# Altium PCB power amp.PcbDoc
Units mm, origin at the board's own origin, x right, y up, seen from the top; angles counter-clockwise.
Board outline 166.75 x 72.39 mm, 2 copper layers (Top Layer, Bottom Layer); 34 components, 39 nets, 126 pads, 16 vias.
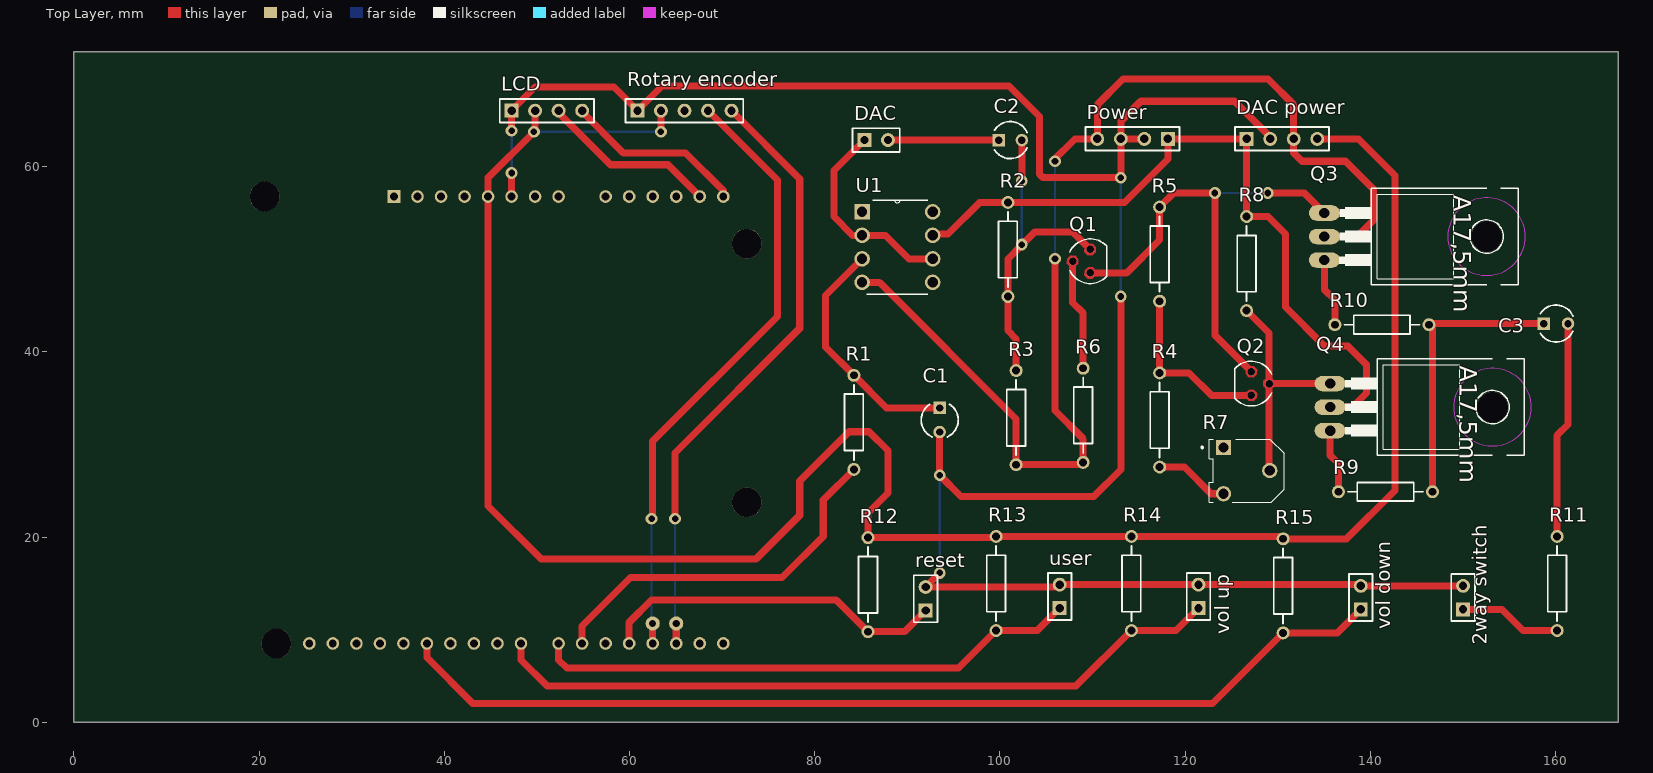
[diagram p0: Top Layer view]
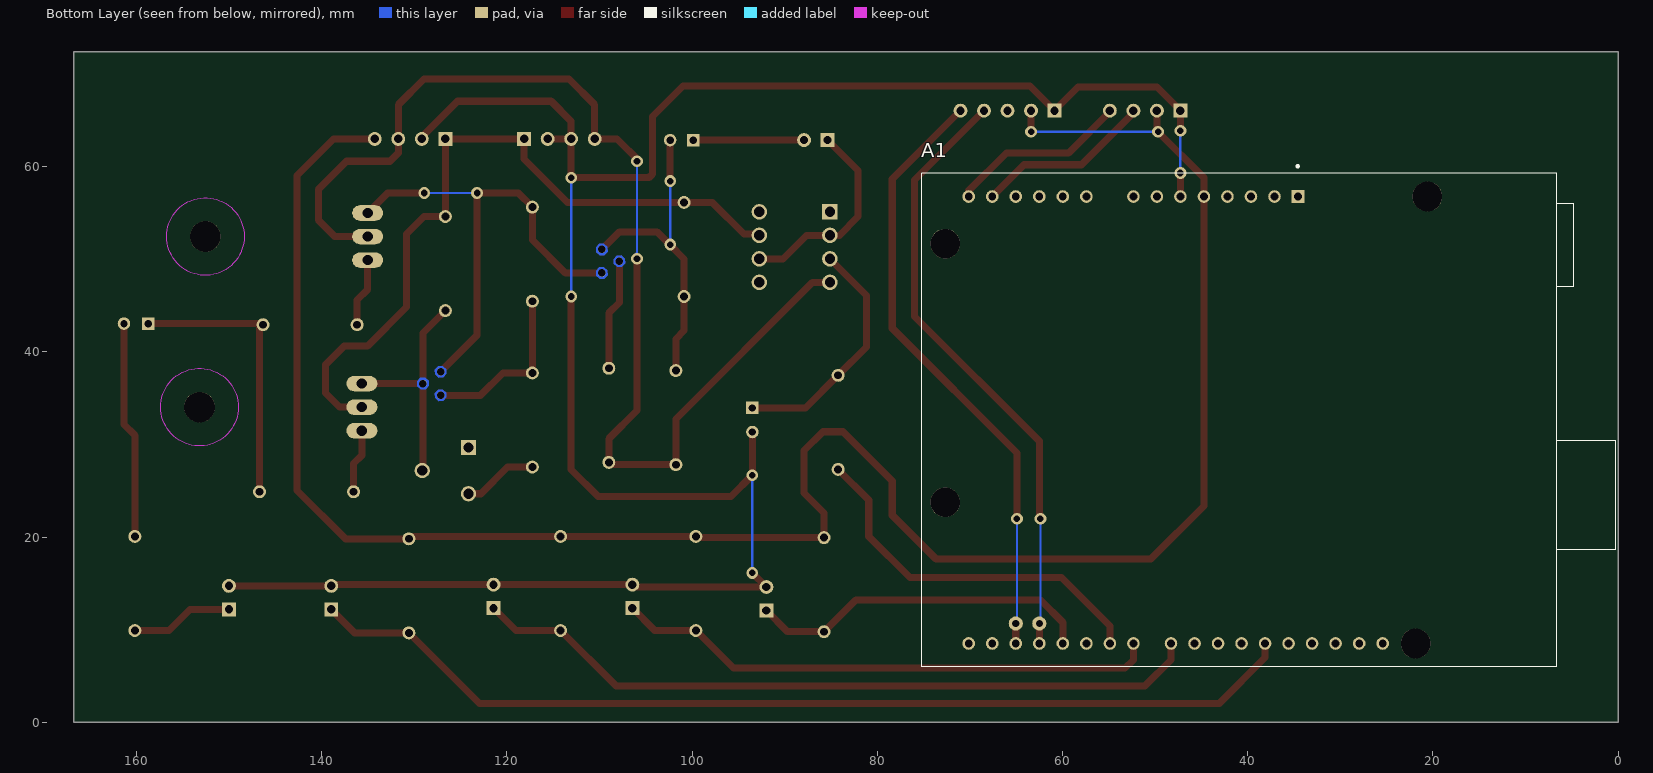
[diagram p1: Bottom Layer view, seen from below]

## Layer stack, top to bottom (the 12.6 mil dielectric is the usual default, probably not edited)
Top Solder: solder mask 0.0102, Solder Resist, Dk 3.5
Top Layer: signal copper 0.0356
Dielectric 1: dielectric 0.32, FR-4, Dk 4.8
Bottom Layer: signal copper 0.0356
Bottom Solder: solder mask 0.0102, Solder Resist, Dk 3.5

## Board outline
0,0 166.751,0 166.751,72.39 0,72.39

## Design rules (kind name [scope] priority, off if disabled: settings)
Clearance [All] p1: gap=0.254 ignorepadtopadclearanceinfootprint=FALSE except(0: Arc-Hole Track-Hole SMDPad-Hole THPad-Hole Via-Hole Fill-Hole Poly-Hole Region-Hole Text-Hole; 0.508: Arc-Arc Arc-Track Arc-THPad Track-Track Track-THPad)
PolygonConnect [All] p1: connectstyle=Relief reliefconductorwidth=0.254 reliefentries=4 polygonreliefangle="90 Angle" airgapwidth=0.254
RoutingVias [All] p1: holewidth=0.711 width=1.27 viastyle="Through Hole" minholewidth=0.711 minwidth=1.27 maxholewidth=0.711 maxwidth=1.27
SolderMaskExpansion [All] p1: expansion=0.102
Width [All] p1: maxlimit=0.813 minlimit=0.254 preferedwidth=0.762 toplayer_minwidth=0.711 bottomlayer_maxwidth=0.254 bottomlayer_prefwidth=0.254 minimp=50.000000 maximp=50.000000 favimp=50.000000
30 further rules are at their usual default settings.

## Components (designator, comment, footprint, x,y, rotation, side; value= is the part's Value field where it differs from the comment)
"2way switch" "Header 2" HDR1X2 150.008,12.192 r90 top
A1 "ARDUINO_UNO_REV3_DEVELOPMENT_BOARD" *ARDUINO_UNO_REV3_DEVELOPMENT_BOARD 40.915,32.639 r270 bottom
C1 "Cap2" CAPR5-4X5#1 93.493,32.639 r270 top value=0.01uF
C2 "Cap2" CAPR5-4X5#2 101.113,62.865 r0 top value=47uF
C3 "Cap2" CAPR5-4X5#1 160.041,43.053 r0 top value=33uF
DAC "Header 2" HDR1X2 85.365,62.865 r0 top
"DAC power" "Header 4" HDR1X4 126.64,62.992 r0 top
LCD "Header 4" HDR1X4 47.265,66.04 r0 top
Power "Header 4" HDR1X4 118.131,62.992 r180 top
Q1 "BC640" *SOT54D_BC640(Primary) 109.749,49.784 r90 top
Q2 "BC639" *SOT54D_BC639(Primary) 127.148,36.576 r270 top
Q3 "TIP125" *TO220 141.372,52.451 r270 top
Q4 "TIP120" *TO220AH_TIP120(Primary) 142.007,34.036 r270 top
R1 "Res2" AXIAL-0.4 84.222,32.385 r90 top value=12K
R2 "Res2" AXIAL-0.4 100.859,51.054 r90 top value=22K
R3 "Res2" AXIAL-0.4 101.748,32.893 r90 top value=15K
R4 "Res2" AXIAL-0.4 117.242,32.639 r270 top value=2.2K
R5 "Res2" AXIAL-0.4 117.242,50.546 r270 top value=4.7K
R6 "Res2" AXIAL-0.4 108.987,33.147 r90 top value=4.7K
R7 "3306F-1-104" *TRIM_3306F-1-104 126.64,27.178 r180 top
R8 "Res2" AXIAL-0.4 126.64,49.53 r90 top value=10K
R9 "Res2" AXIAL-0.4 141.626,24.892 r180 top value=1
R10 "Res2" AXIAL-0.4 141.245,42.926 r0 top value=1
R11 "Res2" AXIAL-0.4 160.168,14.986 r90 top value=1K
R12 "Res2" AXIAL-0.4 85.746,14.859 r270 top value=12K
R13 "Res2" AXIAL-0.4 99.589,14.986 r270 top value=12K
R14 "Res2" AXIAL-0.4 114.194,14.986 r270 top value=12K
R15 "Res2" AXIAL-0.4 130.577,14.732 r270 top value=12K
reset "Header 2" HDR1X2 91.969,12.065 r90 top
"Rotary encoder" "Header 5" HDR1X5 60.854,66.04 r0 top
U1 "TL071CP" *DIP254P762X508-8 92.731,47.498 r0 top
user "Header 2" HDR1X2 106.447,12.319 r90 top
"vol down" "Header 2" HDR1X2 138.959,12.192 r90 top
"vol up" "Header 2" HDR1X2 121.433,12.319 r90 top

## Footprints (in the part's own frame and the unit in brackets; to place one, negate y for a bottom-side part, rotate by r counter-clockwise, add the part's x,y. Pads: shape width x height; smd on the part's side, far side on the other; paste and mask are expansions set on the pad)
*ARDUINO_UNO_REV3_DEVELOPMENT_BOARD [mm]
  rect 1.358x1.358 hole 0.85: 1(-24.13,6.35)
  round 1.358 hole 0.85: 2(-24.13,3.81) 3(-24.13,1.27) 4(-24.13,-1.27) 5(-24.13,-3.81) 6(-24.13,-6.35) 7(-24.13,-8.89) 8(-24.13,-11.43) 9(-24.13,-16.51) 10(-24.13,-19.05) 11(-24.13,-21.59) 12(-24.13,-24.13) 13(-24.13,-26.67) 14(-24.13,-29.21) 15(24.13,-29.21) 16(24.13,-26.67) 17(24.13,-24.13) 18(24.13,-21.59) 19(24.13,-19.05) 20(24.13,-16.51) 21(24.13,-13.97) 22(24.13,-11.43) 23(24.13,-7.366) 24(24.13,-4.826) 25(24.13,-2.286) 26(24.13,0.254) 27(24.13,2.794) 28(24.13,5.334) 29(24.13,7.874) 30(24.13,10.414) 31(24.13,12.954) 32(24.13,15.494)
  round 3.2 hole 3.2 unplated: None(-24.13,20.32) None(-19.05,-31.75) None(8.89,-31.75) None(24.13,19.05)
  silkscreen extent -27.52,-34.29 26.67,40.64
*DIP254P762X508-8 [mil]
  rect 66x66 hole 44: 1(-300,300)
  round 66 hole 44: 2(-300,200) 3(-300,100) 4(-300,0) 5(0,0) 6(0,100) 7(0,200) 8(0,300)
  silkscreen extent -280,-50 -20,350
*SOT54D_BC639(Primary) [mil]
  round 32 hole 32: B(50,0) C(0,75) E(-50,0)
  Top Layer region: -25.57,8.89 -39.01,23.56 -58.89,24.43 -73.56,10.99 -74.43,-8.89 -60.99,-23.56 -41.11,-24.43 -26.44,-10.99
  Top Layer region: 24.43,83.89 10.99,98.56 -8.89,99.43 -23.56,85.99 -24.43,66.11 -10.99,51.44 8.89,50.57 23.56,64.01
  Top Layer region: 74.43,8.89 60.99,23.56 41.11,24.43 26.44,10.99 25.57,-8.89 39.01,-23.56 58.89,-24.43 73.56,-10.99
  Bottom Layer region: -25.57,8.89 -39.01,23.56 -58.89,24.43 -73.56,10.99 -74.43,-8.89 -60.99,-23.56 -41.11,-24.43 -26.44,-10.99
  Bottom Layer region: 24.43,83.89 10.99,98.56 -8.89,99.43 -23.56,85.99 -24.43,66.11 -10.99,51.44 8.89,50.57 23.56,64.01
  Bottom Layer region: 74.43,8.89 60.99,23.56 41.11,24.43 26.44,10.99 25.57,-8.89 39.01,-23.56 58.89,-24.43 73.56,-10.99
  Multi-Layer region: -25.57,8.89 -39.01,23.56 -58.89,24.43 -73.56,10.99 -74.43,-8.89 -60.99,-23.56 -41.11,-24.43 -26.44,-10.99
  Multi-Layer region: 24.43,83.89 10.99,98.56 -8.89,99.43 -23.56,85.99 -24.43,66.11 -10.99,51.44 8.89,50.57 23.56,64.01
  Multi-Layer region: 74.43,8.89 60.99,23.56 41.11,24.43 26.44,10.99 25.57,-8.89 39.01,-23.56 58.89,-24.43 73.56,-10.99
  silkscreen extent -95,-70 95,87
*SOT54D_BC640(Primary) [mil]
  round 32 hole 32: B(50,0) C(0,75) E(-50,0)
  Top Layer region: -25.57,8.89 -39.01,23.56 -58.89,24.43 -73.56,10.99 -74.43,-8.89 -60.99,-23.56 -41.11,-24.43 -26.44,-10.99
  Top Layer region: 24.43,83.89 10.99,98.56 -8.89,99.43 -23.56,85.99 -24.43,66.11 -10.99,51.44 8.89,50.57 23.56,64.01
  Top Layer region: 74.43,8.89 60.99,23.56 41.11,24.43 26.44,10.99 25.57,-8.89 39.01,-23.56 58.89,-24.43 73.56,-10.99
  Bottom Layer region: -25.57,8.89 -39.01,23.56 -58.89,24.43 -73.56,10.99 -74.43,-8.89 -60.99,-23.56 -41.11,-24.43 -26.44,-10.99
  Bottom Layer region: 24.43,83.89 10.99,98.56 -8.89,99.43 -23.56,85.99 -24.43,66.11 -10.99,51.44 8.89,50.57 23.56,64.01
  Bottom Layer region: 74.43,8.89 60.99,23.56 41.11,24.43 26.44,10.99 25.57,-8.89 39.01,-23.56 58.89,-24.43 73.56,-10.99
  Multi-Layer region: -25.57,8.89 -39.01,23.56 -58.89,24.43 -73.56,10.99 -74.43,-8.89 -60.99,-23.56 -41.11,-24.43 -26.44,-10.99
  Multi-Layer region: 24.43,83.89 10.99,98.56 -8.89,99.43 -23.56,85.99 -24.43,66.11 -10.99,51.44 8.89,50.57 23.56,64.01
  Multi-Layer region: 74.43,8.89 60.99,23.56 41.11,24.43 26.44,10.99 25.57,-8.89 39.01,-23.56 58.89,-24.43 73.56,-10.99
  silkscreen extent -95,-70 95,87
*TO220 [mil]
  oval 66x132 hole 44: 1(-100,-250) 2(0,-250) 3(100,-250)
  round 130 hole 130 unplated: None(0,440)
  Keep-Out Layer circle w0: c0,440 r165
  Keep-Out Layer circle w0: c0,440 r165
  Keep-Out Layer circle w0: c0,440 r165
  Keep-Out Layer circle w0: c0,440 r165
  Keep-Out Layer circle w0: c0,440 r165
  Keep-Out Layer circle w0: c0,440 r165
  silkscreen extent -205,-185 205,575
*TO220AH_TIP120(Primary) [mil]
  oval 66x132 hole 44: B(-100,-250) C(0,-250) E(100,-250)
  round 130 hole 130 unplated: None(0,440)
  Keep-Out Layer circle w0: c0,440 r165
  Keep-Out Layer circle w0: c0,440 r165
  Keep-Out Layer circle w0: c0,440 r165
  Keep-Out Layer circle w0: c0,440 r165
  Keep-Out Layer circle w0: c0,440 r165
  Keep-Out Layer circle w0: c0,440 r165
  silkscreen extent -205,-185 205,575
*TRIM_3306F-1-104 [mm]
  rect 1.65x1.65 hole 1.1: 1(2.5,-2.5)
  round 1.65 hole 1.1: 2(-2.5,0) 3(2.5,2.5)
  silkscreen extent -4.05,-3.4 4.9,3.4
AXIAL-0.4 [mm] "Axial Device, Thru-Hole; 2 Leads; 0.4 in Pin Spacing"
  round 1.4 hole 0.85: 1(-5.08,0) 2(5.08,0)
  silkscreen extent -4.06,-1.02 4.06,1.02
CAPR5-4X5#1 [mm] "Capacitor; 2 Leads"
  rect 1.35x1.35 hole 0.8: 1(-1.3,0)
  round 1.35 hole 0.8: 2(1.3,0)
  silkscreen extent -1.69,-2 1.82,2
CAPR5-4X5#2 [mm] "Capacitor; 2 Leads"
  rect 1.35x1.35 hole 0.8: 1(-1.25,0)
  round 1.35 hole 0.8: 2(1.25,0)
  silkscreen extent -1.69,-2 1.82,2
HDR1X2 [mm] "Connector; Header; 2 Position"
  rect 1.5x1.5 hole 0.9: 1(0,0)
  round 1.5 hole 0.9: 2(2.54,0)
  silkscreen extent -1.27,-1.27 3.81,1.27
HDR1X4 [mm] "Connector; Header; 4 Position"
  rect 1.5x1.5 hole 0.9: 1(0,0)
  round 1.5 hole 0.9: 2(2.54,0) 3(5.08,0) 4(7.62,0)
  silkscreen extent -1.27,-1.27 8.89,1.27
HDR1X5 [mm] "Connector; Header; 5 Position"
  rect 1.5x1.5 hole 0.9: 1(0,0)
  round 1.5 hole 0.9: 2(2.54,0) 3(5.08,0) 4(7.62,0) 5(10.16,0)
  silkscreen extent -1.27,-1.27 11.43,1.27

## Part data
"2way switch" DAC reset user "vol down" "vol up": "Header, 2-Pin"
A1: "Plated Through Hole Protoboard Arduino Mega Platform Evaluation Expansion Board", Package=None
C1 C2 C3: "Capacitor"
"DAC power" LCD Power: "Header, 4-Pin"
Q1: "Bipolar _BJT_ Transistor PNP 80V 500mA 150MHz 625mW Through Hole TO-92-3", Package="TO-92 Continental Device"
Q2: "Bipolar _BJT_ Transistor NPN 80V 1A 200MHz 625mW Through Hole TO-92-3", Package="TO-92 Continental Device"
Q3: "Bipolar _BJT_ Transistor PNP - Darlington 60V 5A 2W Through Hole TO-220-3", Package="TO-220 Fairchild Semiconductor"
Q4: "Bipolar _BJT_ Transistor NPN - Darlington 60V 5A 2W Through Hole TO-220-3", Package="TO-220-3 Bourns"
R1 R2 R3 R4 R5 R6 R8 R9 R10 R11 R12 R13 R14 R15: "Resistor"
R7: "100 kOhms 0.2W, 1/5W PC Pins Through Hole Trimmer Potentiometer Cermet 1 Turn Top Adjustment", Package="6432 Bourns"
"Rotary encoder": "Header, 5-Pin"
U1: "J-FET Amplifier 1 Circuit 8-PDIP", Package="DIP-8 Texas Instruments"

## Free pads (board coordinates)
  round 1.524 hole 0.762: 2(62.505,10.668) 3(65.045,10.668)

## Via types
v1: diameter 1.27, hole 0.711, Top Layer to Bottom Layer, 16 vias

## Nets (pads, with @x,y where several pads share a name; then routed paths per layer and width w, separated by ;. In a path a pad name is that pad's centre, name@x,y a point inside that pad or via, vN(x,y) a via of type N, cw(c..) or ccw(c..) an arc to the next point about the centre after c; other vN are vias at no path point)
+5V: "DAC power.4" "Rotary encoder.2" A1.5 LCD.2 R12.1 R13.1 R14.1 R15.1 | length 228.2
  Top Layer w0.762: v1@49.551,63.881 v1(49.678,63.754) ; LCD.2@49.805,65.532 49.805,63.881 v1(49.678,63.754) ; v1(63.394,63.754) 63.394,66.04 ; 134.26,62.992 138.705,62.992 142.642,59.055 142.642,25.019 137.435,19.812 R15.1 130.323,20.066 R14.1 R13.1 99.462,19.939 R12.1 85.746,22.606 87.905,24.765 87.905,29.337 85.873,31.369 83.714,31.369 78.38,26.035 78.38,22.352 73.681,17.653 50.44,17.653 44.725,23.368 A1.5 44.725,58.801 v1(49.678,63.754)
  Bottom Layer w0.254: v1(49.678,63.754) v1(63.394,63.754)
+15V: "DAC power.1" Power.1 Q4.C R2.2 R8.2 U1.7 | length 79.7
  Top Layer w0.762: U1.7 92.858,52.705 94.382,52.705 97.811,56.134 R2.2 113.432,56.134 118.131,60.833 Power.1 126.64,62.992 R8.2 128.926,54.61 130.831,52.705 130.831,44.831 135.022,40.64 137.562,40.64 139.594,38.608 139.594,35.56 138.07,34.036 Q4.C
-15V: "DAC power.3" Power.4 Q3.2 R3.1 R6.1 U1.4 | length 127.2
  Top Layer w0.762: U1.4 87.016,47.498 101.748,32.766 R3.1 108.86,27.813 R6.1@108.987,27.94 ; v1(105.939,50.038) 105.939,33.655 108.987,30.607 R6.1 ; v1(105.939,60.579) 105.685,60.579 108.098,62.992 Power.4 110.511,66.675 113.305,69.469 128.926,69.469 131.72,66.675 131.72,62.992 131.72,61.468 132.609,60.579 137.308,60.579 140.356,57.531 140.356,54.229 138.578,52.451 Q3.2
  Bottom Layer w0.254: v1(105.939,50.038) 106.256,50.355 105.939,50.673 v1(105.939,60.579)
A0: A1.9
A1: A1.10
A2: A1.11
A3: A1.12
CLK: "Rotary encoder.5" A1.17 pad.3 | length 66.3
  Top Layer w0.762: v1(64.918,21.971) 64.918,29.083 78.38,42.545 78.38,58.674 71.014,66.04 ; A1.17@64.996,8.509 A1.17 pad.3
  Bottom Layer w0.254: v1(64.918,21.971) 64.918,10.795 pad.3
D0: A1.15
D1: A1.16
D4: A1.19 R12.2 reset.1 | length 37.7
  Top Layer w0.762: A1.19 59.965,10.795 62.378,13.208 82.317,13.208 R12.2 89.683,9.779 reset.1
D5: A1.20
D6: A1.21 R1.1 | length 40.5
  Top Layer w0.762: A1.21 54.885,10.414 60.092,15.621 76.475,15.621 80.92,20.066 80.92,24.003 R1.1
D7: A1.22 R13.2 user.1 | length 58.9
  Top Layer w0.762: A1.22 52.345,6.731 53.234,5.842 95.525,5.842 R13.2 104.034,9.906 user.1
D8: "vol up.1" A1.23 R14.2 | length 79.6
  Top Layer w0.762: A1.23 48.281,6.731 51.075,3.937 108.225,3.937 R14.2 119.02,9.906 121.433,12.319
D9: A1.24
D10: A1.25
D11: A1.26
D12: "vol down.1" A1.27 R15.2 | length 108.6
  Top Layer w0.762: A1.27 38.121,6.985 43.074,2.032 122.957,2.032 R15.2 136.419,9.652 138.959,12.192
D13: A1.28
"DAC in": DAC.1 U1.2 U1.6 | length 22.2
  Top Layer w0.762: DAC.1 82.063,59.563 82.063,54.61 84.095,52.578 U1.2 87.651,52.578 90.191,50.038 U1.6
"DAC out": C2.1 DAC.2 | length 12
  Top Layer w0.762: DAC.2 C2.1
DT: "Rotary encoder.4" A1.18 pad.2 | length 66.7
  Top Layer w0.762: v1(62.378,21.971) 62.505,21.844 62.505,30.353 75.967,43.815 75.967,58.547 68.474,66.04 ; pad.2 A1.18 A1.18@62.681,8.509
  Bottom Layer w0.254: v1(62.378,21.971) 62.378,10.795 pad.2
GND: "2way switch.2" "DAC power.2" "Rotary encoder.1" "vol down.2" "vol up.2" A1.6 C1.2 LCD.1 Power.2 Power.3 reset.2 user.2 | length 242.4
  Top Layer w0.762: A1.6 v1(47.265,59.309) ; v1(47.265,63.881) LCD.1 49.805,68.58 58.314,68.58 60.854,66.04 63.521,68.707 100.986,68.707 104.288,65.405 104.288,59.182 104.669,58.801 v1(113.051,58.801) Power.3 ; v1@93.366,26.797 v1(93.493,26.67) ; v1(93.493,16.129) reset.2 106.193,14.605 user.2 121.433,14.859 138.832,14.859 138.959,14.732 150.008,14.732 ; C1.2 v1(93.493,26.67) ; v1(113.051,45.974) 113.051,27.305 110.13,24.384 95.779,24.384 v1(93.493,26.67) ; Power.2 Power.3 ; 129.18,62.992 129.18,63.209 125.333,67.056 115.21,67.056 113.051,64.897 Power.3
  Bottom Layer w0.254: v1(47.265,59.309) v1(47.265,63.881) ; v1(93.493,16.129) v1(93.493,26.67) ; v1(113.051,45.974) v1(113.051,58.801)
NetC1_1: C1.1 R1.2 U1.3 | length 26.2
  Top Layer w0.762: U1.3 81.174,46.101 81.174,40.513 R1.2 87.748,33.939 C1.1
NetC2_2: C2.2 Q1.B R2.1 R3.2 | length 34.6
  Top Layer w0.762: R3.2 101.748,41.402 100.859,42.291 R2.1 100.859,50.038 v1@102.383,51.562 ; v1(102.363,51.582) v1@102.383,51.562 ; v1(102.363,58.44) C2.2 ; Q1.B 107.844,52.959 103.78,52.959 v1@102.383,51.562
  Bottom Layer w0.254: v1(102.363,51.582) v1(102.363,58.44)
NetC3_1: C3.1 R9.1 R10.2 | length 30.7
  Top Layer w0.762: R9.1 146.706,42.545 R10.2 146.452,43.053 C3.1
NetC3_2: C3.2 R11.2 | length 23.5
  Top Layer w0.762: R11.2 160.168,30.988 161.341,32.161 C3.2
NetQ1_C: Q1.C R6.2 | length 12
  Top Layer w0.762: Q1.C 107.844,45.339 108.987,44.196 R6.2
NetQ1_E: Q1.E Q2.E Q3.1 R5.1 | length 52.8
  Top Layer w0.762: Q1.E 113.686,48.514 117.242,52.07 R5.1 118.766,57.15 v1(123.211,57.15) 123.211,41.783 Q2.E ; v1(128.926,57.15) 132.863,57.15 Q3.1
  Bottom Layer w0.254: v1(123.211,57.15) v1(128.926,57.15)
NetQ2_B: Q2.B R4.1 R5.2 | length 18.7
  Top Layer w0.762: R5.2@117.115,45.466 117.242,45.339 R4.1 120.417,37.719 122.83,35.306 Q2.B
NetQ2_C: Q2.C Q4.B R7.2 R8.1 | length 25.2
  Top Layer w0.762: R8.1 129.053,42.037 Q2.C ; Q2.C@128.799,36.576 Q2.C ; R7.2 129.053,27.265 Q2.C ; Q4.B Q2.C
NetQ3_3: Q3.3 R10.1 | length 7.5
  Top Layer w0.762: Q3.3 135.022,46.736 136.165,45.593 R10.1
NetQ4_E: Q4.E R9.2 | length 7
  Top Layer w0.762: Q4.E 135.657,28.829 136.546,27.94 R9.2
NetR4_2: R4.2 R7.3 | length 8.1
  Top Layer w0.762: R4.2 119.909,27.559 122.79,24.678 R7.3
Out: "2way switch.1" R11.1 | length 11.1
  Top Layer w0.762: 150.008,12.192 154.199,12.192 156.485,9.906 R11.1
SCL: A1.14 LCD.4 | length 19.6
  Top Layer w0.762: LCD.4@54.758,66.04 59.33,61.468 66.061,61.468 70.125,57.404 A1.14
SDA: A1.13 LCD.3 | length 19.3
  Top Layer w0.762: LCD.3@52.091,66.04 57.933,60.198 64.156,60.198 A1.13
SW: "Rotary encoder.3"
pads on no net: A1.1 A1.2 A1.3 A1.4 A1.7 A1.8 A1.29 A1.30 A1.31 A1.32 A1.None Q3.None Q4.None R7.1 U1.1 U1.5 U1.8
